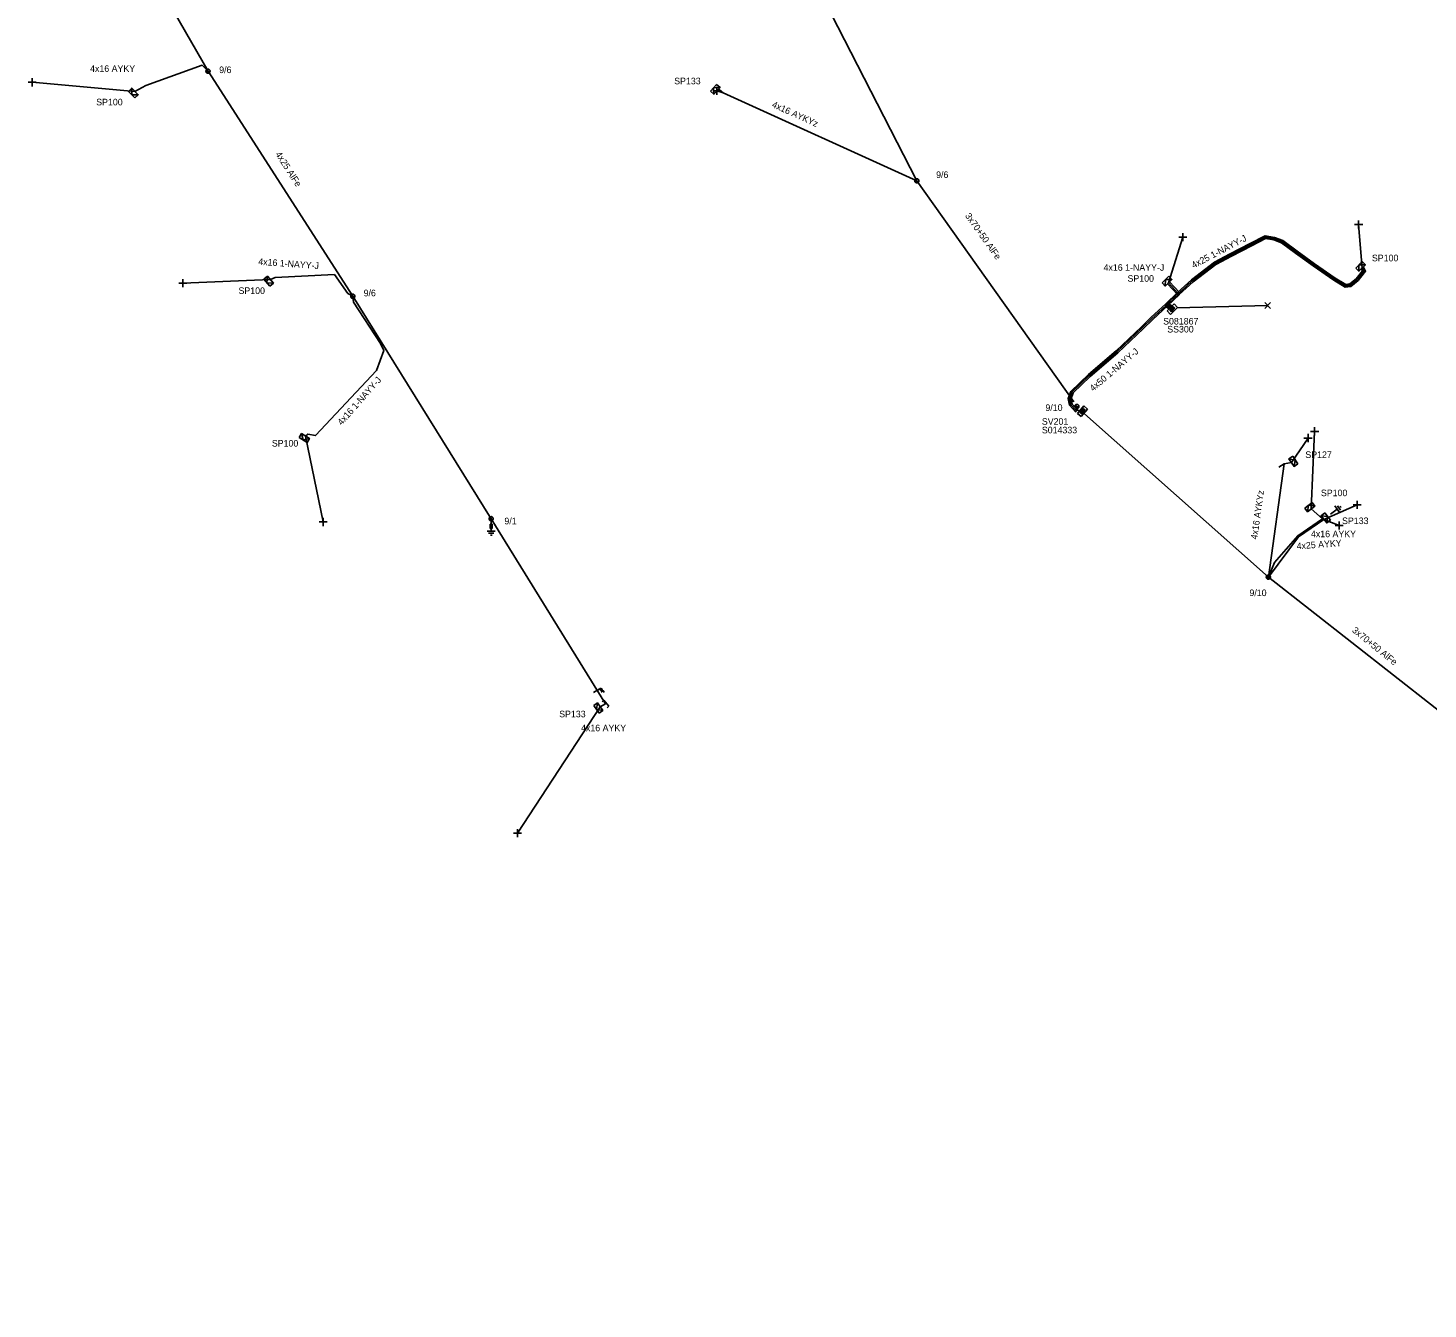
# Model space of a CAD drawing. Extents: x -717562 to -713845, y -1151196 to -1143903.
# Drawn here: x -714644.3 to -714431.8, y -1145872.2 to -1145677.8 of the extents above; entities that cross this region are included whole.
import ezdxf

# ---------------------------------------------------------------- set-up
doc = ezdxf.new("R2010")
doc.units = 0
for name, color, linetype in [('Vrstva 1', 7, 'Continuous'), ('Vrstva 12', 7, 'Continuous'), ('Vrstva 13', 7, 'Continuous'), ('Vrstva 14', 7, 'Continuous'), ('Vrstva 15', 7, 'Continuous'), ('Vrstva 16', 7, 'Continuous'), ('Vrstva 18', 7, 'Continuous'), ('Vrstva 2', 7, 'Continuous'), ('Vrstva 20', 7, 'Continuous'), ('Vrstva 28', 7, 'Continuous'), ('Vrstva 29', 7, 'Continuous'), ('Vrstva 30', 7, 'Continuous'), ('Vrstva 31', 7, 'Continuous'), ('Vrstva 33', 7, 'Continuous'), ('Vrstva 34', 7, 'Continuous'), ('Vrstva 5', 7, 'Continuous'), ('Vrstva 52', 7, 'Continuous'), ('Vrstva 54', 7, 'Continuous'), ('Vrstva 55', 7, 'Continuous'), ('Vrstva 59', 7, 'Continuous'), ('Vrstva 6', 7, 'Continuous'), ('Vrstva 8', 7, 'Continuous'), ('Vrstva 9', 7, 'Continuous')]:
    doc.layers.add(name, color=color, linetype=linetype)

# ---------------------------------------------------------------- blocks, each defined once
blk = doc.blocks.new('NN440')
at = {"layer": 'Vrstva 2'}
for points in [[(0.63, 0), (0.63, 0.06), (0.62, 0.13), (0.6, 0.19), (0.58, 0.25), (0.55, 0.31), (0.51, 0.37), (0.47, 0.42), (0.42, 0.46), (0.37, 0.51), (0.32, 0.54), (0.26, 0.57), (0.2, 0.59), (0.13, 0.61), (0.07, 0.62), (0, 0.63), (-0.06, 0.62), (-0.13, 0.61), (-0.19, 0.59), (-0.26, 0.57), (-0.31, 0.54), (-0.37, 0.51), (-0.42, 0.46), (-0.47, 0.42), (-0.51, 0.37), (-0.54, 0.31), (-0.57, 0.25), (-0.6, 0.19), (-0.62, 0.13), (-0.63, 0.06), (-0.63, 0), (-0.63, -0.07), (-0.62, -0.14), (-0.6, -0.2), (-0.57, -0.26), (-0.54, -0.32), (-0.51, -0.37), (-0.47, -0.43), (-0.42, -0.47), (-0.37, -0.51), (-0.31, -0.55), (-0.26, -0.58), (-0.19, -0.6), (-0.13, -0.62), (-0.06, -0.63), (0, -0.63), (0.07, -0.63), (0.13, -0.62), (0.2, -0.6), (0.26, -0.58), (0.32, -0.55), (0.37, -0.51), (0.42, -0.47), (0.47, -0.43), (0.51, -0.37), (0.55, -0.32), (0.58, -0.26), (0.6, -0.2), (0.62, -0.14), (0.63, -0.07), (0.63, 0)], [(-0.63, 0), (0.63, 0)], [(-0.6, -0.18), (0.57, -0.18)], [(-0.51, -0.32), (0.5, -0.32)], [(-0.37, -0.47), (0.35, -0.47)]]:
    blk.add_lwpolyline(points, dxfattribs=at)
blk = doc.blocks.new('NN840')
at = {"layer": 'Vrstva 15'}
for points in [[(0, 0.62), (0, -0.63)], [(-0.75, -0.71), (-0.75, -0.66)], [(-0.73, -0.76), (-0.75, -0.71)], [(-0.66, -0.8), (-0.73, -0.76)], [(-0.63, -0.8), (-0.66, -0.8)], [(-0.56, -0.76), (-0.63, -0.8)], [(-0.54, -0.71), (-0.56, -0.76)], [(-0.54, -0.38), (-0.54, -0.71)], [(-0.33, -0.38), (-0.33, -0.8)], [(-0.33, -0.64), (-0.13, -0.38)], [(-0.26, -0.56), (-0.09, -0.8)]]:
    blk.add_lwpolyline(points, dxfattribs=at)
blk = doc.blocks.new('NN800')
at = {"layer": 'Vrstva 1'}
for points in [[(-0.44, 0.44), (0.44, -0.44)], [(-0.44, -0.44), (0.44, 0.44)]]:
    blk.add_lwpolyline(points, dxfattribs=at)
blk = doc.blocks.new('NN820')
at = {"layer": 'Vrstva 13'}
for points in [[(0, 0), (0, -1.05)], [(-0.16, -0.81), (0.16, -0.81)], [(-0.16, -1.47), (-0.16, -0.81)], [(0.16, -1.47), (-0.16, -1.47)], [(0, -1.05), (-0.06, -0.93)], [(0, -1.05), (0.06, -0.93)], [(0, -1.47), (0, -1.87)], [(0.16, -0.81), (0.16, -1.47)]]:
    blk.add_lwpolyline(points, dxfattribs=at)
blk = doc.blocks.new('NN620')
at = {"layer": 'Vrstva 8'}
for points in [[(0.75, 0), (-0.75, 0)], [(-0.75, 0), (-0.75, -0.75)], [(0.75, -0.75), (0.75, 0)], [(-0.75, -0.75), (0.75, -0.75)], [(0.37, -0.18), (-0.38, -0.18)], [(-0.38, -0.18), (-0.38, -0.56)], [(-0.38, -0.56), (0.37, -0.56)], [(0.32, -0.23), (-0.33, -0.23)], [(-0.33, -0.23), (-0.33, -0.51)], [(-0.33, -0.51), (0.32, -0.51)], [(0.27, -0.27), (-0.28, -0.27)], [(-0.28, -0.27), (-0.28, -0.46)], [(-0.28, -0.46), (0.27, -0.46)], [(0.23, -0.32), (-0.23, -0.32)], [(-0.23, -0.32), (-0.23, -0.42)], [(-0.23, -0.42), (0.23, -0.42)], [(-0.19, -0.37), (0.19, -0.37)], [(0.23, -0.42), (0.23, -0.32)], [(0.27, -0.46), (0.27, -0.27)], [(0.32, -0.51), (0.32, -0.23)], [(0.37, -0.56), (0.37, -0.18)]]:
    blk.add_lwpolyline(points, dxfattribs=at)
blk = doc.blocks.new('NN630')
at = {"layer": 'Vrstva 9'}
for points in [[(0, -0.7), (-0.7, 0)], [(-0.7, -0.7), (-0.7, 0), (0.7, 0), (0.7, -0.7)], [(-0.7, -0.7), (0.7, -0.7)], [(0, -0.7), (0.7, 0)]]:
    blk.add_lwpolyline(points, dxfattribs=at)
blk = doc.blocks.new('NN810')
at = {"layer": 'Vrstva 14'}
for points in [[(0.63, -1.89), (-0.62, -1.89)], [(0, -0.64), (0, -1.89)], [(0.39, -2.2), (-0.4, -2.2)], [(0, -2.52), (-0.12, -2.52)], [(0.14, -2.52), (0, -2.52)]]:
    blk.add_lwpolyline(points, dxfattribs=at)
blk = doc.blocks.new('NN510')
at = {"layer": 'Vrstva 2'}
blk.add_lwpolyline([(0, 0), (0, 0.94)], dxfattribs=at)
blk = doc.blocks.new('NN515')
at = {"layer": 'Vrstva 2'}
for points in [[(-0.59, 0.18), (0.59, 0.18)], [(-0.59, 0.18), (-0.59, -0.18)], [(0.59, 0.18), (0.59, -0.18)]]:
    blk.add_lwpolyline(points, dxfattribs=at)

msp = doc.modelspace()

# ---------------------------------------------------------------- linework, layer by layer
at = {"layer": 'Vrstva 1'}
for points in [[(-714485.57, -1145734.52), (-714509.39, -1145700.95), (-714526.39, -1145667.75), (-714539.76, -1145638.14)], [(-714556.65, -1145780.38), (-714574.01, -1145752.25), (-714595.01, -1145718.48), (-714616.99, -1145684.31), (-714629.01, -1145663.37), (-714639.53, -1145643.84)], [(-714483.95, -1145736.31), (-714456.03, -1145761.11), (-714424.39, -1145785.94), (-714393.7, -1145804.17), (-714367.32, -1145819.73), (-714338.57, -1145836.69), (-714309.37, -1145856.78), (-714285.43, -1145872.23)]]:
    msp.add_lwpolyline(points, dxfattribs=at)
at = {"layer": 'Vrstva 20'}
for points in [[(-714469.81, -1145717.91), (-714467.7, -1145716), (-714464.22, -1145713.31), (-714461.82, -1145712.05), (-714458.78, -1145710.48), (-714456.52, -1145709.3), (-714455.11, -1145709.54), (-714453.85, -1145710), (-714451.65, -1145711.63), (-714449.01, -1145713.55), (-714445.88, -1145715.71), (-714444.27, -1145716.69), (-714443.67, -1145716.61), (-714442.7, -1145715.81), (-714441.74, -1145714.64), (-714441.95, -1145714.29), (-714441.61, -1145714.09), (-714441.26, -1145714.68), (-714442.42, -1145716.09), (-714443.51, -1145716.99), (-714444.35, -1145717.11), (-714446.1, -1145716.05), (-714449.25, -1145713.87), (-714451.89, -1145711.95), (-714454.05, -1145710.36), (-714455.21, -1145709.92), (-714456.46, -1145709.72), (-714458.6, -1145710.84), (-714461.64, -1145712.41), (-714464, -1145713.65), (-714467.44, -1145716.3), (-714469.55, -1145718.21)], [(-714469.83, -1145718.2), (-714471.32, -1145716.58), (-714471.02, -1145716.3), (-714469.53, -1145717.92)], [(-714471.6, -1145719.65), (-714469.82, -1145717.92), (-714469.54, -1145718.2), (-714471.32, -1145719.93)], [(-714471.32, -1145719.94), (-714473.57, -1145722), (-714475.02, -1145723.42), (-714478.89, -1145727.09), (-714483.08, -1145730.66), (-714485.68, -1145733.16), (-714485.98, -1145734.01), (-714485.81, -1145734.85), (-714485.4, -1145735.33), (-714485.28, -1145735.1), (-714484.92, -1145735.3), (-714485.32, -1145736.03), (-714486.19, -1145735.03), (-714486.4, -1145733.99), (-714486.02, -1145732.94), (-714483.34, -1145730.36), (-714479.15, -1145726.79), (-714475.3, -1145723.14), (-714473.85, -1145721.7), (-714471.6, -1145719.64)], [(-714471.02, -1145720.42), (-714471.62, -1145720.04), (-714471.3, -1145719.54), (-714470.7, -1145719.92)]]:
    msp.add_lwpolyline(points, close=True, dxfattribs=at)
at = {"layer": 'Vrstva 5'}
for points in [[(-714470.75, -1145720), (-714471.23, -1145719.7), (-714469.47, -1145717.99), (-714469.27, -1145717.69), (-714467.57, -1145716.15), (-714464.11, -1145713.48), (-714461.73, -1145712.23), (-714458.69, -1145710.66), (-714456.49, -1145709.51), (-714455.16, -1145709.73), (-714453.95, -1145710.18), (-714451.77, -1145711.79), (-714449.13, -1145713.71), (-714445.99, -1145715.88), (-714444.31, -1145716.9), (-714443.59, -1145716.8), (-714442.56, -1145715.95), (-714441.5, -1145714.66), (-714441.78, -1145714.19)], [(-714484.65, -1145735.85), (-714485.36, -1145735.68), (-714486, -1145734.94), (-714486.19, -1145734), (-714485.85, -1145733.05), (-714483.21, -1145730.51), (-714479.02, -1145726.94), (-714475.16, -1145723.28), (-714473.71, -1145721.85), (-714471.61, -1145719.93), (-714470.97, -1145720.34)]]:
    msp.add_lwpolyline(points, dxfattribs=at)
at = {"layer": 'Vrstva 52'}
for points in [[(-714616.99, -1145684.31), (-714617.89, -1145683.41), (-714626.42, -1145686.48), (-714628.08, -1145687.38)], [(-714595.01, -1145718.48), (-714595.76, -1145718.04), (-714597.81, -1145715.16), (-714606.78, -1145715.64), (-714607.52, -1145715.96)], [(-714470.86, -1145720.17), (-714471.55, -1145719.73), (-714469.75, -1145717.99), (-714471.17, -1145716.44)], [(-714595.01, -1145718.48), (-714594.92, -1145719.36), (-714590.82, -1145725.64), (-714590.31, -1145726.7), (-714591.4, -1145729.74), (-714600.66, -1145739.62), (-714601.82, -1145739.42), (-714602.19, -1145739.7)], [(-714456.03, -1145761.11), (-714455.1, -1145758.88), (-714451.56, -1145754.84), (-714447.81, -1145752.28), (-714449.52, -1145750.76)], [(-714456.03, -1145761.11), (-714451.45, -1145754.98), (-714447.59, -1145752.35)], [(-714556.65, -1145780.38), (-714557.47, -1145780.79)]]:
    msp.add_lwpolyline(points, dxfattribs=at)
at = {"layer": 'Vrstva 54'}
for points in [[(-714509.39, -1145700.95), (-714538.77, -1145687.61), (-714539.73, -1145687.3)], [(-714456.03, -1145761.11), (-714453.61, -1145743.93), (-714452.52, -1145743.73)]]:
    msp.add_lwpolyline(points, dxfattribs=at)
at = {"layer": 'Vrstva 59'}
for points in [[(-714628.08, -1145687.38), (-714643.69, -1145686)], [(-714441.78, -1145714.19), (-714442.33, -1145707.59)], [(-714471.17, -1145716.44), (-714469.01, -1145709.5)], [(-714607.52, -1145715.96), (-714620.81, -1145716.5)], [(-714469.92, -1145720.22), (-714456.13, -1145719.88)], [(-714602.18, -1145739.7), (-714599.5, -1145752.75)], [(-714452.52, -1145743.73), (-714450, -1145740)], [(-714449.52, -1145750.76), (-714449, -1145739)], [(-714447.59, -1145752.35), (-714442.54, -1145750.15)], [(-714447.59, -1145752.35), (-714445.27, -1145753.28)], [(-714557.47, -1145780.79), (-714570, -1145800)]]:
    msp.add_lwpolyline(points, dxfattribs=at)

# ---------------------------------------------------------------- block references
at = {"layer": 'Vrstva 13'}
for p, xscale, yscale, rotation in [((-714616.99, -1145684.31), 0.5, 0.5, -61.06082501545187), ((-714509.39, -1145700.95), 0.5, 0.5, -57.13655277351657), ((-714595.01, -1145718.48), 0.5, 0.49999999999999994, -57.248674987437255), ((-714485.09, -1145735.2), 0.49999999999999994, 0.5000000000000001, -40.80850544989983), ((-714574.01, -1145752.25), 0.5, 0.49999999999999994, -58.12177772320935), ((-714456.03, -1145761.11), 0.49999999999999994, 0.5000000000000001, -38.88763899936)]:
    msp.add_blockref('NN440', p, dxfattribs=dict(at, xscale=xscale, yscale=yscale, rotation=rotation))
for name, p, rotation in [('NN510', (-714538.77, -1145687.61), 52.13819724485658), ('NN510', (-714453.61, -1145743.93), 120.98266669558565), ('NN515', (-714556.65, -1145780.38), -50.06553341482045)]:
    msp.add_blockref(name, p, dxfattribs=dict(at, rotation=rotation))
at = {"layer": 'Vrstva 15', "rotation": 125.55504448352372}
msp.add_blockref('NN810', (-714447.12, -1145751.91), dxfattribs=at)
at = {"layer": 'Vrstva 15'}
msp.add_blockref('NN810', (-714574.01, -1145752.25), dxfattribs=at)
at = {"layer": 'Vrstva 16'}
msp.add_blockref('NN820', (-714574.01, -1145752.25), dxfattribs=at)
at = {"layer": 'Vrstva 18', "rotation": 121.68494724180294}
msp.add_blockref('NN840', (-714557.92, -1145778.32), dxfattribs=at)
at = {"layer": 'Vrstva 28'}
for p, rotation in [((-714470.86, -1145720.17), 44.35623512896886), ((-714484.52, -1145735.69), 49.191000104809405)]:
    msp.add_blockref('NN620', p, dxfattribs=dict(at, rotation=rotation))
at = {"layer": 'Vrstva 31'}
for p, rotation in [((-714628.08, -1145687.38), -45), ((-714539.73, -1145687.3), -132.2940417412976), ((-714441.78, -1145714.19), -134.63503531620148), ((-714607.52, -1145715.96), -48.983880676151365), ((-714471.17, -1145716.44), -136.20602823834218), ((-714602.19, -1145739.7), -31.521775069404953), ((-714452.52, -1145743.73), 123.76428612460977), ((-714449.52, -1145750.76), -142.47200836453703), ((-714447.59, -1145752.35), 128.1693889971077), ((-714557.47, -1145780.79), -54.56668610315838)]:
    msp.add_blockref('NN630', p, dxfattribs=dict(at, rotation=rotation))
at = {"layer": 'Vrstva 34'}
for p, rotation in [((-714643.69, -1145686), 44.99999995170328), ((-714539.73, -1145687.3), 45), ((-714442.33, -1145707.59), 45), ((-714469.01, -1145709.5), 45), ((-714620.81, -1145716.5), 45), ((-714456.13, -1145719.88), -0.12622650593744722), ((-714450, -1145740), 45), ((-714449, -1145739), 45), ((-714442.54, -1145750.15), 45), ((-714599.5, -1145752.75), 45), ((-714445.27, -1145753.28), 45), ((-714570, -1145800), 45)]:
    msp.add_blockref('NN800', p, dxfattribs=dict(at, rotation=rotation))

# ---------------------------------------------------------------- texts
at = {"layer": 'Vrstva 12'}
for s, p in [('9/6', (-714615.29, -1145684.6)), ('9/6', (-714506.46, -1145700.53)), ('9/6', (-714593.37, -1145718.49)), ('9/10', (-714489.87, -1145735.89)), ('9/1', (-714572, -1145753.1)), ('9/10', (-714458.9, -1145764))]:
    msp.add_text(s, height=1, dxfattribs=at).set_placement(p)
at = {"layer": 'Vrstva 2'}
for s, rotation, p in [('4x25 AlFe', 302.751, (-714606.82, -1145696.91)), ('3x70+50 AlFe', 305.356, (-714502.12, -1145706.27)), ('3x70+50 AlFe', 321.041, (-714443.41, -1145769.36))]:
    msp.add_text(s, height=1, rotation=rotation, dxfattribs=at).set_placement(p)
at = {"layer": 'Vrstva 29'}
for s, p in [('S081867', (-714472, -1145722.77)), ('S014333', (-714490.41, -1145739.29))]:
    msp.add_text(s, height=1, dxfattribs=at).set_placement(p)
at = {"layer": 'Vrstva 30'}
for s, p in [('SS300', (-714471.38, -1145723.98)), ('SV201', (-714490.41, -1145737.99))]:
    msp.add_text(s, height=1, dxfattribs=at).set_placement(p)
at = {"layer": 'Vrstva 33'}
for s, p in [('SP133', (-714546.22, -1145686.3)), ('SP100', (-714633.96, -1145689.5)), ('SP100', (-714440.31, -1145713.17)), ('SP100', (-714477.41, -1145716.28)), ('SP100', (-714612.36, -1145718.13)), ('SP100', (-714607.3, -1145741.3)), ('SP127', (-714450.41, -1145743.03)), ('SP100', (-714448.05, -1145748.83)), ('SP133', (-714444.84, -1145753.07)), ('SP133', (-714563.68, -1145782.4))]:
    msp.add_text(s, height=1, dxfattribs=at).set_placement(p)
at = {"layer": 'Vrstva 54'}
for s, p in [('4x16 AYKY', (-714634.89, -1145684.42)), ('4x16 1-NAYY-J', (-714481.04, -1145714.61)), ('4x16 AYKY', (-714449.56, -1145755.06)), ('4x16 AYKY', (-714560.36, -1145784.52))]:
    msp.add_text(s, height=1, dxfattribs=at).set_placement(p)
for s, rotation, p in [('4x16 1-NAYY-J', 355.903, (-714609.38, -1145713.7)), ('4x16 1-NAYY-J', 48.491, (-714596.7, -1145738.15)), ('4x25 AYKY', 4.161, (-714451.7, -1145756.91))]:
    msp.add_text(s, height=1, rotation=rotation, dxfattribs=at).set_placement(p)
at = {"layer": 'Vrstva 55'}
for rotation, p in [(335.579, (-714531.48, -1145689.72)), (81.983, (-714457.72, -1145755.44))]:
    msp.add_text('4x16 AYKYz', height=1, rotation=rotation, dxfattribs=at).set_placement(p)
at = {"layer": 'Vrstva 6'}
for s, rotation, p in [('4x25 1-NAYY-J', 27.709, (-714467.38, -1145714.28)), ('4x50 1-NAYY-J', 40.432, (-714482.63, -1145732.99))]:
    msp.add_text(s, height=1, rotation=rotation, dxfattribs=at).set_placement(p)

doc.saveas('drawing.dxf')
